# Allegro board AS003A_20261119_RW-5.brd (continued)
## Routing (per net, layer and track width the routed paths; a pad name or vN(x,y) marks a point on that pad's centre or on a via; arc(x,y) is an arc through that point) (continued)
D231_MCB1_CT2:
  vias: v1(180.11,297.94)
D431_MCB1_CT1:
  vias: v1(180.11,295.15)
D10101: length 119.1
  L05_DIG w0.081: 287.63,201.55 289.67,199.51 289.67,192.61 294.07,188.22 294.07,178.98 292.8,177.71 292.8,111.06 D101.01
  L05_DIG w0.102: 287.63,201.55 287.63,205.83 v1(287.23,206.23)
D10102: length 242.3
  L03_DIG w0.096: 298.03,201.55 298.03,201.53 298.05,201.51 298.05,201.08 298.64,200.49 299.02,200.49 300.17,199.34 300.17,189.72 301.57,188.32 301.57,178.57 305.12,175.02 305.12,166.06 304.4,165.34 304.4,112.25 294.99,102.84 294.99,87.93 296.56,86.36 302.52,86.36 304.06,87.9 304.06,105.98 307.95,109.86 307.95,144.51 308.72,145.29 310.6,145.29 312.5,143.39 312.5,117.55 311.54,116.59 311.54,100.72 D101.02
  L03_DIG w0.102: 298.03,201.55 298.03,202.63 v1(298.43,203.03)
D10103: length 119.2
  L05_DIG w0.081: 291.63,201.55 291.63,201.19 293.25,199.57 293.25,191.81 294.87,190.2 294.87,178.77 296.56,177.07 296.56,169.06 306.87,158.76 306.87,137.44 306.01,136.58 306.01,114.7 311.5,109.22 311.5,97.44 D101.03
  L05_DIG w0.102: 291.63,201.55 291.63,205.83 v1(291.23,206.23)
D10104: length 242.3
  L03_DIG w0.096: 298.43,201.55 298.43,201.53 298.41,201.51 298.41,201.24 298.8,200.85 299.18,200.85 300.54,199.49 300.54,189.87 301.94,188.47 301.94,178.72 305.49,175.17 305.49,165.91 304.77,165.19 304.77,112.1 295.36,102.69 295.36,88.08 296.71,86.73 302.37,86.73 303.69,88.06 303.69,106.13 307.58,110.01 307.58,144.67 308.57,145.66 310.76,145.66 312.87,143.55 312.87,117.4 311.91,116.44 311.91,101.47 312.95,100.43 313.59,100.43 D101.04
  L03_DIG w0.102: 298.43,201.55 v1(298.43,202.23)
D10105: length 119.9
  L05_DIG w0.081: D101.05 316.47,97.55 316.47,104.97 314.68,106.76 314.68,152.92 297.94,169.66 297.94,189.94 295.02,192.86 295.02,199.64 293.23,201.42 293.23,201.55
  L05_DIG w0.102: v1(292.83,206.23) 293.23,205.83 293.23,201.55
D10106: length 193.3
  L03_DIG w0.096: 300.83,201.55 300.83,201.53 300.85,201.51 300.85,200.56 302.17,199.24 302.17,189.88 304.45,187.6 304.45,182.94 305.95,181.45 319.62,181.45 329.72,171.35 329.72,111.68 328.77,110.73 327.31,110.73 326.12,111.92 326.12,136.43 322.21,140.34 319.92,140.34 317.87,138.29 317.87,130.26 323.21,124.92 323.21,101.7 321.86,100.36 321.34,100.36 D101.06
  L03_DIG w0.102: 300.83,201.55 v1(300.83,202.23)
D10107: length 190.1
  L07_DIG w0.081: D101.07 323.96,97.9 323.96,118.56 304.09,138.44 303.79,138.44 303.58,138.23 303.58,137.93 322.96,118.55 322.96,118.29 322.75,118.08 322.42,118.08 302.39,138.1 302.39,152.73 303.38,153.72 303.38,160.48 303.18,160.68 302.88,160.68 302.67,160.47 302.67,156.44 302.46,156.23 302.16,156.23 301.95,156.44 301.95,175.65 302.25,175.95 302.25,199.46 301.69,200.02 298.41,200.02 297.23,201.2 297.23,201.55
  L07_DIG w0.102: 297.23,201.55 297.23,205.03 v1(297.63,205.43)
D10108: length 193.3
  L03_DIG w0.096: 301.23,201.55 301.23,201.53 301.21,201.51 301.21,200.71 302.54,199.39 302.54,190.03 304.82,187.75 304.82,183.1 306.1,181.82 319.77,181.82 330.08,171.51 330.08,111.53 328.92,110.36 327.16,110.36 325.75,111.77 325.75,136.27 322.06,139.97 320.07,139.97 318.24,138.14 318.24,130.41 323.58,125.07 323.58,100.6 D101.08
  L03_DIG w0.102: 301.23,201.55 301.23,202.63 v1(300.83,203.03)
D10109: length 193.3
  L07_DIG w0.081: D101.09 326.45,97.73 326.45,121.18 306.76,140.88 306.46,140.88 306.25,140.67 306.25,140.37 324.7,121.92 324.7,121.63 324.49,121.42 324.19,121.42 304.65,140.96 304.65,153.12 308.27,156.74 308.27,163.13 308.07,163.33 307.77,163.33 307.55,163.11 307.55,157.46 307.34,157.25 307.05,157.25 306.84,157.46 306.84,188.06 304.65,190.25 304.65,199.28 302.93,201 299.16,201 298.83,201.33 298.83,201.55
  L07_DIG w0.102: v1(299.23,205.43) 298.83,205.03 298.83,201.55
D10110: length 122.7
  L03_DIG w0.096: D101.10 332.03,100.89 332.03,171.4 314.96,188.47 305.73,188.47 304.42,189.78 304.42,198.73 302.05,201.1 302.05,201.39 302.03,201.41 302.03,201.55
  L03_DIG w0.102: 302.03,201.55 302.03,202.63 v1(302.43,203.03)
D10111: length 242.3
  L07_DIG w0.081: 303.91,205.83 304.09,205.83 305.65,204.27 305.65,203.5 306.35,202.81 312.33,202.81 317.95,197.18 317.95,192.42 313.2,187.67 313.2,172.48 313.41,172.27 313.7,172.27 313.91,172.48 313.91,186.87 314.12,187.08 314.42,187.08 314.63,186.87 314.63,170.04 313.89,169.3 310.24,169.3 309.26,168.32 309.26,141.34 309.47,141.13 309.77,141.13 309.98,141.34 309.98,167.56 310.19,167.77 310.48,167.77 310.69,167.56 310.69,140.58 319.61,131.67 325.3,131.67 330.19,126.78 330.19,114.82 330.4,114.61 330.69,114.61 330.9,114.82 330.9,122.19 331.11,122.39 331.41,122.39 331.62,122.19 331.62,97.64 D101.11
  L07_DIG w0.102: 303.91,205.83 300.43,205.83 v1(300.03,206.23)
D10112: length 122.7
  L03_DIG w0.096: 302.43,201.55 302.43,201.24 304.79,198.88 304.79,189.93 305.88,188.84 315.11,188.84 332.4,171.56 332.4,101.04 333.18,100.26 334.08,100.26 D101.12
  L03_DIG w0.102: 302.43,201.55 v1(302.43,202.23)
D10113: length 131.6
  L07_DIG w0.081: D101.13 336.6,97.74 336.6,125.16 324.53,137.22 324.53,182.93 318.97,188.49 318.97,197.44 311.84,204.57 306.51,204.57 304.45,206.63 303.91,206.63
  L07_DIG w0.102: v1(300.03,207.03) 300.43,206.63 303.91,206.63
D10114: length 244.5
  L03_DIG w0.096: D101.14 341.85,100.55 343.71,100.55 343.98,100.82 343.98,111.82 348.17,116.01 348.17,155.62 347.07,156.72 340.15,156.72 338.82,155.39 338.82,110.28 337.7,109.16 335.95,109.16 334.99,110.13 334.99,171.49 333.16,173.32 333.16,199.44 330.8,201.8 314.79,201.8 312.14,204.45 305.27,204.45 304.47,205.25 304.15,205.25 303.93,205.03 303.91,205.03
  L03_DIG w0.102: 303.91,205.03 302.83,205.03 v1(302.43,205.43)
D10115: length 140.5
  L07_DIG w0.081: D101.15 341.7,97.72 341.7,123.99 327.32,138.37 327.32,189.27 326.56,190.03 326.56,200.86 325.37,202.06 316.09,202.06 311.65,206.5 305.97,206.5 305.03,207.43 303.91,207.43
  L07_DIG w0.102: v1(300.03,207.83) 300.43,207.43 303.91,207.43
D10116: length 244.5
  L03_DIG w0.096: D101.16 344.35,100.15 344.35,111.67 348.54,115.86 348.54,155.77 347.22,157.09 339.99,157.09 338.45,155.55 338.45,110.43 337.55,109.53 336.11,109.53 335.36,110.28 335.36,171.64 333.52,173.48 333.52,199.59 330.95,202.17 314.94,202.17 312.29,204.82 305.42,204.82 304.62,205.61 304.15,205.61 303.93,205.83 303.91,205.83
  L03_DIG w0.102: 303.91,205.83 302.13,205.83 302.03,205.73 302.03,205.03 v1(302.43,204.63)
D10201: length 212.5
  L30_DIG w0.081: 287.63,201.55 287.63,192.69 286.3,191.36 284,191.36 282.52,189.88 282.52,164.64 290.22,156.94 290.22,108.26 294.34,104.13 294.34,44.16 296.66,41.84 300.46,41.84 302.24,43.62 302.24,71.1 D102.01
  L30_DIG w0.102: 287.63,201.55 287.63,203.43 v1(288.03,203.83)
D10202: length 135.3
  L07_DIG w0.081: 294.03,201.55 294.03,200.38 294.76,199.66 294.76,191.36 294.06,190.66 294.06,178.04 295.42,176.67 295.42,157.18 293.86,155.61 293.86,129.16 305.91,117.11 305.91,82.71 D102.02
  L07_DIG w0.102: 294.03,201.55 294.03,205.03 v1(294.43,205.43)
D10203: length 138.4
  L07_DIG w0.081: D102.03 311.23,77.39 311.23,114.69 295,130.91 295,155.08 296.69,156.77 296.69,176.61 294.91,178.38 294.91,189.32 295.34,189.75 295.34,200.43 294.83,200.94 294.83,201.55
  L07_DIG w0.102: v1(295.23,205.43) 294.83,205.03 294.83,201.55
D10204: length 112.5
  L07_DIG w0.081: D102.04 313.68,80.02 313.68,117.99 297.9,133.77 297.9,181.94 K7.2
D10205: length 159.1
  L09_DIG w0.081: D102.05 316.28,77.42 316.28,108.99 319.25,111.96 319.25,153.73 319.98,154.46 319.98,168.01 325.35,173.38 325.35,189.52 326.7,190.87 326.7,201.14 323.84,204 317.42,204 316.43,204.99 315.29,204.99 311.81,208.47 306.14,208.47 305.58,209.03 303.91,209.03
  L09_DIG w0.102: 303.91,209.03 301.23,209.03 v1(300.83,209.43)
D10206: length 179.1
  L05_DIG w0.079: D102.06 321.39,80.09 322.21,80.09 322.76,80.64 322.76,81.6 321.09,83.27 321.09,105.11 323.06,107.08 323.06,123.19 322.11,124.14 320.91,124.14 319.88,123.12 319.88,107.15 319,106.27 317.75,106.27 316.96,107.07 316.96,134.69 319.06,136.79 319.06,152.94 304.66,167.34 304.66,175.97 301.4,179.22 301.4,188.88 296.65,193.64 296.65,201.19
  L05_DIG w0.102: 296.65,201.19 296.63,201.21 296.63,201.48 296.43,201.68 296.43,204.23 v1(296.83,204.63)
D10207: length 165
  L09_DIG w0.081: 303.91,209.83 312.02,209.83 315.89,205.95 325.56,205.95 331.3,200.21 331.3,194.11 329.83,192.64 329.83,175.39 322.47,168.03 322.47,136.81 324.51,134.76 324.51,124.4 321.35,121.23 321.35,77.43 D102.07
  L09_DIG w0.102: v1(300.83,210.23) 301.23,209.83 303.91,209.83
D10208: length 179.1
  L05_DIG w0.079: D102.08 323.14,80.72 323.14,81.76 321.47,83.43 321.47,104.95 323.45,106.92 323.45,123.35 322.27,124.52 320.75,124.52 319.5,123.28 319.5,107.31 318.84,106.65 317.91,106.65 317.34,107.23 317.34,134.53 319.45,136.63 319.45,153.1 305.04,167.5 305.04,176.13 301.79,179.38 301.79,189.04 297.03,193.8 297.03,201.19
  L05_DIG w0.102: v1(296.83,205.43) 297.23,205.03 297.23,201.68 297.03,201.48 297.03,201.19
D10209: length 165.9
  L09_DIG w0.081: D102.09 326.54,77.32 326.54,133.34 329.93,136.73 329.93,165.77 334.06,169.9 334.06,201.16 328.45,206.76 316.28,206.76 312.84,210.21 305.89,210.21 305.46,210.63 303.91,210.63
  L09_DIG w0.102: v1(300.83,211.03) 301.23,210.63 303.91,210.63
D10210: length 215.3
  L05_DIG w0.079: D102.10 332.17,80.71 332.17,82.46 331.31,83.31 331.31,106.07 332.43,107.18 332.43,139.74 331.83,140.34 329.52,140.34 328.8,139.63 328.8,106.81 327.78,105.79 325.96,105.79 324.87,106.88 324.87,149.89 307.79,166.97 307.79,186.79 304.33,190.25 304.33,195.79 302.28,197.84 301,197.84 300.15,198.69 300.15,199.37 299.81,199.72 299.38,199.72 298.25,200.84 298.25,201.23
  L05_DIG w0.102: 298.25,201.23 298.23,201.25 298.23,201.51 298.03,201.71 298.03,205.03 v1(298.43,205.43)
D10211: length 170.2
  L09_DIG w0.081: 303.91,211.43 313.13,211.43 316.97,207.59 329.96,207.59 339.71,197.84 339.71,140.29 331.56,132.14 331.56,77.38 D102.11
  L09_DIG w0.102: v1(300.83,211.83) 301.23,211.43 303.91,211.43
D10212: length 215.2
  L05_DIG w0.079: 298.63,201.23 298.63,201 299.54,200.1 299.97,200.1 300.53,199.53 300.53,198.85 301.16,198.22 302.44,198.22 304.72,195.94 304.72,190.41 308.18,186.95 308.18,167.12 325.25,150.05 325.25,107.04 326.12,106.18 327.62,106.18 328.42,106.97 328.42,139.78 329.36,140.73 331.99,140.73 332.81,139.9 332.81,107.02 331.7,105.91 331.7,83.47 332.55,82.62 332.55,80.65 333.24,79.96 334.06,79.96 D102.12
  L05_DIG w0.102: v1(298.43,204.63) 298.83,204.23 298.83,201.71 298.63,201.51 298.63,201.23
D10213: length 175.8
  L09_DIG w0.081: D102.13 336.62,77.4 336.62,134.8 344.46,142.64 344.46,168.47 343.2,169.74 343.2,196.94 330.6,209.53 317.14,209.53 314.64,212.03 306.09,212.03 305.09,213.03 303.91,213.03
  L09_DIG w0.102: v1(299.23,212.63) 299.63,213.03 303.91,213.03
D10214: length 190.1
  L05_DIG w0.079: 300.65,201.21 300.65,200.74 301.18,200.21 316.48,200.21 318.68,198.01 318.68,188.65 321.06,186.27 336.86,186.27 352.89,170.23 352.89,141.08 365.1,128.87 365.1,89.99 357.89,82.78 343.82,82.78 343.01,81.96 343.01,80.49 342.45,79.93 341.55,79.93 D102.14
  L05_DIG w0.102: v1(300.83,204.63) 300.43,204.23 300.43,201.69 300.63,201.49 300.63,201.23 300.65,201.21
D10215: length 177
  L09_DIG w0.081: D102.15 341.72,77.38 341.72,135.52 347.41,141.21 347.41,168.2 344.89,170.73 344.89,198.98 333.5,210.37 317.89,210.37 314.43,213.83 303.91,213.83
  L09_DIG w0.102: v1(300.83,214.23) 301.23,213.83 303.91,213.83
D10216: length 190.1
  L05_DIG w0.079: D102.16 343.39,80.79 343.39,81.8 343.98,82.39 358.04,82.39 365.49,89.83 365.49,129.03 353.28,141.24 353.28,170.39 337.01,186.65 321.22,186.65 319.07,188.81 319.07,198.17 316.64,200.6 301.33,200.6 301.03,200.9 301.03,201.21
  L05_DIG w0.102: v1(300.83,205.43) 301.23,205.03 301.23,201.69 301.03,201.49 301.03,201.21
D10301: length 215.3
  L32_DIG w0.081: 298.83,201.55 298.83,201.25 299.87,200.21 301.06,200.21 302.17,199.1 302.17,135.27 276.43,109.53 276.43,41.23 280.75,36.91 288.37,36.91 D103.01
  L32_DIG w0.102: 298.83,201.55 298.83,202.63 v1(299.23,203.03)
D10302: length 209.9
  L30_DIG w0.081: D103.02 308.64,59.66 308.64,104.21 305.84,107.02 295.5,107.02 292.76,109.76 292.76,118.05 294.05,119.34 294.05,150.88 293.84,151.1 293.54,151.1 293.34,150.9 293.34,128.76 293.14,128.56 292.84,128.56 292.62,128.78 292.62,158.1 284.92,165.8 284.92,175.76 285.7,176.54 285.7,188.97 288.26,191.54 288.26,199.63 288.43,199.79 288.43,201.55
  L30_DIG w0.102: 288.43,201.55 288.43,203.43 v1(288.83,203.83)
D10303: length 153
  L32_DIG w0.081: D103.03 311.32,56.98 311.32,127.58 304.54,134.37 304.54,199.4 303.51,200.43 301.66,200.43 301.23,200.85 301.23,201.55
  L32_DIG w0.102: v1(301.63,203.03) 301.23,202.63 301.23,201.55
D10304: length 209.9
  L30_DIG w0.081: D103.04 313.68,59.7 313.68,109.17 309.47,113.38 303.15,113.38 297.91,118.62 297.91,141.77 297.7,141.98 297.4,141.98 297.19,141.77 297.19,119.08 296.98,118.87 296.68,118.87 296.47,119.08 296.47,142.97 297.91,144.41 297.91,154.94 286.8,166.04 286.8,176.05 288.78,178.03 288.78,190.28 289.52,191.02 289.52,199.93 289.23,200.22 289.23,201.55
  L30_DIG w0.102: 289.23,201.55 289.23,203.43 v1(289.63,203.83)
D10305: length 193.3
  L32_DIG w0.081: D103.05 316.33,57.05 316.33,107.29 324.65,115.6 324.65,136.87 322.36,139.16 322.36,174.71 318.72,178.36 318.72,192.68 318.51,192.88 318.22,192.88 318,192.66 318,182.97 317.79,182.76 317.49,182.76 317.28,182.97 317.28,201.09 311.74,206.63 303.91,206.63
  L32_DIG w0.102: 303.91,206.63 299.63,206.63 v1(299.23,206.23)
D10306: length 158.7
  L30_DIG w0.081: 290.83,201.55 290.83,200.31 290.06,199.54 290.06,184.6 289.6,184.14 289.6,166.68 302.3,153.97 302.3,125.5 318.81,109 318.81,59.65 D103.06
  L30_DIG w0.102: v1(291.23,203.83) 290.83,203.43 290.83,201.55
D10307: length 176.5
  L32_DIG w0.081: D103.07 321.54,56.92 321.54,108.49 327.78,114.72 327.78,189.03 326.66,190.16 326.66,201.44 325.19,202.91 316.86,202.91 311.59,208.17 305.25,208.17 304.51,207.43 303.91,207.43
  L32_DIG w0.102: v1(302.43,207.83) 302.83,207.43 303.91,207.43
D10308: length 179.1
  L30_DIG w0.081: 291.63,201.55 291.63,200.03 291.26,199.67 291.26,184.33 290.42,183.48 290.42,178.13 292.55,176 292.55,165.8 304.52,153.83 304.52,131.07 312.52,123.07 312.82,123.07 313.03,123.28 313.03,123.58 307.26,129.34 307.26,129.63 307.47,129.84 307.77,129.84 323.87,113.75 323.87,59.67 D103.08
  L30_DIG w0.102: v1(292.03,203.83) 291.63,203.43 291.63,201.55
D10309: length 180.5
  L32_DIG w0.081: D103.09 326.52,57.02 326.52,107.17 330.47,111.13 330.47,189.56 331.7,190.79 331.7,199.99 327.41,204.28 317.49,204.28 312.03,209.74 306.03,209.74 305.32,209.03 303.91,209.03
  L32_DIG w0.102: 303.91,209.03 302.83,209.03 v1(302.43,209.43)
D10310: length 179.1
  L30_DIG w0.081: D103.10 328.8,59.82 328.8,114.14 310.55,132.39 310.26,132.39 310.05,132.18 310.05,131.88 315.36,126.57 315.36,126.25 315.15,126.04 314.87,126.04 306.86,134.05 306.86,155.64 296.65,165.85 296.65,175.31 294.09,177.86 294.09,189.29 291.84,191.54 291.84,199.39 292.43,199.98 292.43,201.55
  L30_DIG w0.102: v1(292.83,203.83) 292.43,203.43 292.43,201.55
D10311: length 183.4
  L32_DIG w0.081: D103.11 331.68,56.94 331.68,104.77 333.21,106.3 333.21,154.7 331.61,156.31 331.61,167.83 332.87,169.09 332.87,202.15 329.1,205.92 316.85,205.92 312.59,210.18 311.24,210.18 309.88,211.54 306.06,211.54 305.15,210.63 303.91,210.63
  L32_DIG w0.102: 303.91,210.63 302.83,210.63 v1(302.43,211.03)
D10312: length 188.5
  L30_DIG w0.081: 293.23,201.55 293.23,191.63 294.92,189.94 294.92,178.57 297.86,175.64 297.86,169.5 309.1,158.25 309.1,137.05 320.27,125.89 320.54,125.89 320.75,126.1 320.75,126.42 312.57,134.59 312.57,134.89 312.78,135.1 313.08,135.1 334,114.18 334,59.7 D103.12
  L30_DIG w0.102: 293.23,201.55 293.23,203.43 v1(293.63,203.83)
D10313: length 184.5
  L32_DIG w0.081: 303.91,212.23 306.05,212.23 306.26,212.02 311.96,212.02 317.22,206.75 330.62,206.75 334.5,202.87 334.5,168.58 335.25,167.83 335.25,105.11 336.64,103.73 336.64,57.06 D103.13
  L32_DIG w0.102: v1(302.43,212.63) 302.83,212.23 303.91,212.23
D10314: length 188.5
  L30_DIG w0.081: D103.14 339.14,59.64 339.14,115.94 327.68,127.4 327.68,127.69 327.89,127.9 328.18,127.9 335.77,120.32 336.06,120.32 336.27,120.53 336.27,120.83 310.27,146.83 310.27,168.62 302.95,175.94 300.43,175.94 297.84,178.53 297.84,189.12 295.2,191.76 295.2,199.91 294.83,200.29 294.83,201.55
  L30_DIG w0.102: 294.83,201.55 294.83,203.43 v1(295.23,203.83)
D10315: length 188.1
  L32_DIG w0.081: D103.15 341.71,57.07 341.71,124.16 337.47,128.4 337.47,201.3 331.06,207.71 317.21,207.71 311.09,213.83 303.91,213.83
  L32_DIG w0.102: v1(302.43,214.23) 302.83,213.83 303.91,213.83
D10316: length 209.5
  L30_DIG w0.081: 295.63,201.55 295.63,200.55 296.8,199.38 296.8,193.02 301.11,188.7 301.11,179.62 311.73,169 311.73,147 341.97,116.76 342.27,116.76 342.48,116.97 342.48,117.27 328,131.75 328,132.04 328.21,132.25 328.51,132.25 344.19,116.57 344.19,59.67 D103.16
  L30_DIG w0.102: v1(296.03,203.83) 295.63,203.43 295.63,201.55
D10401: length 184.6
  L34_DIG w0.102: v1(288.83,206.23) 288.43,205.83 288.43,201.55
  L34_DIG w0.104: 288.43,201.55 288.43,199.75 288.21,199.54 288.21,192.07 285.74,189.6 283.85,189.6 282.62,188.37 282.62,173.53 293.46,162.69 293.46,49.44 D104.01
D10402: length 209.9
  L34_DIG w0.102: v1(289.63,202.23) 289.63,201.55
  L34_DIG w0.104: D104.02 303.18,44.8 303.18,63.14 303.39,63.35 303.7,63.35 303.92,63.14 303.92,47.27 304.18,47.01 304.49,47.01 304.66,47.17 304.66,153.06 287.2,170.51 287.2,174.6 285.84,175.96 285.84,188.64 289.63,192.43 289.63,201.55
D10403: length 177.5
  L34_DIG w0.102: 290.43,201.55 v1(290.43,202.23)
  L34_DIG w0.104: 290.43,201.55 290.43,200.48 291.14,199.77 291.14,191.42 289.09,189.37 289.09,172.58 310.23,151.45 310.23,108.4 311.32,107.31 311.32,36.66 D104.03
D10404: length 175.5
  L34_DIG w0.102: 291.23,201.55 v1(291.23,202.23)
  L34_DIG w0.104: D104.04 313.64,39.42 313.64,109.01 311.8,110.85 311.8,151.79 289.95,173.64 289.95,184.68 291.83,186.55 291.83,199.93 291.23,200.53 291.23,201.55
D10405: length 179.1
  L34_DIG w0.102: 292.03,201.55 v1(292.03,202.23)
  L34_DIG w0.104: D104.05 316.25,36.81 316.25,110.17 312.79,113.63 312.79,152.72 292.46,173.05 292.46,176.04 290.67,177.83 290.67,184.2 292.99,186.52 292.99,199.52 292.03,200.48 292.03,201.55
D10406: length 192
  L34_DIG w0.102: v1(293.63,206.23) 293.23,205.83 293.23,201.55
  L34_DIG w0.104: D104.06 318.63,39.51 318.63,111.61 314.67,115.56 314.67,139.15 316.79,141.26 316.79,153.6 317.77,154.59 317.77,168.46 314.84,171.4 297.66,171.4 296.74,172.32 296.74,174.53 294.08,177.19 294.08,183.39 293.61,183.87 293.61,199.99 293.23,200.37 293.23,201.55
D10407: length 195.5
  L34_DIG w0.102: 294.03,201.55 294.03,205.83 v1(294.43,206.23)
  L34_DIG w0.104: 294.03,201.55 294.03,200.47 294.8,199.7 294.8,178.08 297.13,175.74 315.4,175.74 319.97,171.17 319.97,154.88 319.15,154.06 319.15,137.73 317.38,135.96 317.38,127.78 319.94,125.23 319.94,113.81 321.44,112.31 321.44,36.7 D104.07
D10408: length 188.5
  L34_DIG w0.102: v1(295.23,202.23) 295.23,201.55
  L34_DIG w0.104: D104.08 323.72,39.5 323.72,112.34 321.88,114.18 321.88,126.33 318.68,129.54 318.68,133.56 322.49,137.38 322.49,170.13 315.54,177.09 300.4,177.09 298.09,179.4 298.09,190.52 295.23,193.37 295.23,201.55
D10409: length 209.5
  L34_DIG w0.102: v1(296.03,202.23) 296.03,201.55
  L34_DIG w0.104: D104.09 326.39,36.83 326.39,127.95 326.07,128.27 325.24,128.27 325.04,128.08 325.04,118 324.83,117.79 324.4,117.79 324.18,118.01 324.18,173.59 317.33,180.44 303.59,180.44 301.41,182.62 301.41,188.62 297.07,192.96 297.07,199.97 296.03,201.01 296.03,201.55
D10410: length 190.1
  L34_DIG w0.102: v1(296.83,206.23) 297.23,205.83 297.23,201.55
  L34_DIG w0.104: 297.23,201.55 297.23,201.17 298.65,199.76 298.65,195.62 302.31,191.95 302.31,187.1 304.83,184.57 304.83,182.97 305.51,182.29 319.39,182.29 327.7,173.97 327.7,103.55 328.86,102.39 328.86,39.44 D104.10
D10411: length 193.3
  L34_DIG w0.102: 298.03,201.55 298.03,205.83 v1(297.63,206.23)
  L34_DIG w0.104: D104.11 331.57,36.73 331.57,103.1 329.37,105.29 329.37,174.34 318.33,185.38 306.6,185.38 304.15,187.83 304.15,192.16 302.39,193.92 302.39,198.93 301.64,199.68 299.62,199.68 298.03,201.27 298.03,201.55
D10412: length 215.2
  L34_DIG w0.102: v1(299.23,202.23) 299.23,201.55
  L34_DIG w0.104: D104.12 333.86,39.52 333.86,107.21 330.88,110.19 330.88,124.52 331.1,124.74 331.4,124.74 331.62,124.52 331.62,112.48 331.85,112.25 332.16,112.25 332.36,112.45 332.36,177.05 323.04,186.38 309.5,186.38 308.06,187.82 308.06,188.86 305.12,191.8 305.12,196.23 303.97,197.38 303.97,199.51 303.02,200.46 300.15,200.46 299.23,201.38 299.23,201.55
D10413: length 191.7
  L34_DIG w0.102: 300.03,201.55 v1(300.03,202.23)
  L34_DIG w0.104: 300.03,201.55 300.31,201.27 303.42,201.27 304.83,199.86 304.83,197.67 306.91,195.59 306.91,191.98 311,187.89 323.95,187.89 334.93,176.92 334.93,110.89 336.64,109.19 336.64,36.74 D104.13
D10414: length 188.9
  L34_DIG w0.102: 303.91,202.19 303.87,202.23 v1(303.23,202.23)
  L34_DIG w0.104: D104.14 339.11,39.35 339.11,136.81 339.79,137.49 339.79,179.04 330.58,188.24 326.02,188.24 324.35,189.91 320.36,189.91 318.82,191.44 318.82,193.08 311.77,200.14 305.97,200.14 303.91,202.19
D10415: length 199.1
  L34_DIG w0.102: 303.91,203.03 v1(303.23,203.03)
  L34_DIG w0.104: D104.15 341.82,36.64 341.82,134.84 347.97,140.99 347.97,175.46 332.58,190.85 327.48,190.85 326.16,192.18 320.39,192.18 309.99,202.58 305.22,202.58 304.77,203.03 303.91,203.03
D10416: length 199.9
  L34_DIG w0.102: 303.91,203.83 v1(303.23,203.83)
  L34_DIG w0.104: 303.91,203.83 305.13,203.83 305.89,203.07 311,203.07 321.09,192.98 332.81,192.98 334.89,190.9 337.08,190.9 349.62,178.35 349.62,129.63 344.26,124.27 344.26,39.28 D104.16
D10501: length 181.6
  L05_DIG w0.081: D105.01 373.28,104.24 373.28,194.88 364.78,203.38 318.13,203.38 313.37,208.15 305.81,208.15 304.93,209.03 303.91,209.03
  L05_DIG w0.102: 303.91,209.03 299.63,209.03 v1(299.23,209.43)
D10502: length 314.6
  L03_DIG w0.096: 303.91,207.03 303.93,207.03 303.95,207.05 304.61,207.05 305.41,206.24 312.68,206.24 315.58,203.34 333.23,203.34 335.24,201.33 387.98,201.33 393.86,195.45 393.86,136.05 392.9,135.09 391.71,135.09 390.58,136.22 390.58,191.16 389.1,192.63 387.12,192.63 385.88,191.4 385.88,137.01 386.74,136.16 386.74,100.77 386.46,100.49 384.97,100.49 D105.02
  L03_DIG w0.102: 303.91,207.03 v1(303.23,207.03)
D10503: length 190
  L07_DIG w0.081: D105.03 384.97,97.63 384.97,194.54 380.56,198.95 374.57,198.95 373.25,200.26 335.3,200.26 331.62,203.94 317.46,203.94 311.85,209.55 305.39,209.55 304.86,209.03 303.91,209.03
  L07_DIG w0.102: 303.91,209.03 300.43,209.03 v1(300.03,209.43)
D10504: length 314.6
  L03_DIG w0.096: D105.04 387.11,100.57 387.11,136.31 386.25,137.16 386.25,191.24 387.28,192.27 388.95,192.27 390.21,191.01 390.21,136.07 391.56,134.72 393.05,134.72 394.23,135.9 394.23,195.6 388.13,201.7 335.4,201.7 333.39,203.71 315.73,203.71 312.84,206.61 305.57,206.61 304.76,207.41 303.95,207.41 303.93,207.43 303.91,207.43
  L03_DIG w0.102: v1(302.43,207.03) 302.83,207.43 303.91,207.43
D10505: length 194.5
  L07_DIG w0.081: 303.91,210.63 304.07,210.63 304.56,210.14 312.61,210.14 316.36,206.39 331.1,206.39 336.13,201.36 381.86,201.36 390.16,193.06 390.16,97.52 D105.05
  L07_DIG w0.102: 303.91,210.63 300.43,210.63 v1(300.03,211.03)
D10506: length 314.6
  L03_DIG w0.096: 303.91,208.23 303.93,208.23 303.95,208.25 305,208.25 305.24,208 315.97,208 317.06,206.91 332.37,206.91 336.29,202.99 423.51,202.99 424.26,202.24 424.26,201.11 423.66,200.51 394.78,200.51 393.73,199.46 393.73,198.08 394.78,197.03 424.17,197.03 425.03,196.17 425.03,194.46 423.83,193.27 399.53,193.27 395.83,189.56 395.83,101.19 D105.06
  L03_DIG w0.102: 303.91,208.23 302.83,208.23 v1(302.43,208.63)
D10507: length 199.7
  L07_DIG w0.081: 303.91,211.43 313.15,211.43 317,207.59 331.7,207.59 336.61,202.68 385.29,202.68 395.29,192.68 395.29,97.47 D105.07
  L07_DIG w0.102: 303.91,211.43 300.43,211.43 v1(300.03,211.83)
D10508: length 314.6
  L03_DIG w0.096: 303.91,208.63 303.93,208.63 303.95,208.61 305.15,208.61 305.4,208.37 316.13,208.37 317.22,207.27 332.52,207.27 336.44,203.36 423.66,203.36 424.63,202.39 424.63,200.96 423.81,200.14 394.93,200.14 394.1,199.3 394.1,198.23 394.93,197.4 424.32,197.4 425.4,196.32 425.4,194.31 423.98,192.9 399.69,192.9 396.2,189.41 396.2,101.34 397.25,100.29 397.55,100.29 D105.08
  L03_DIG w0.102: 303.91,208.63 v1(303.23,208.63)
D10509: length 207.5
  L07_DIG w0.081: D105.09 400.24,97.6 400.24,137.59 401.66,139.01 401.66,193.38 391.23,203.81 375.7,203.81 372.87,206.64 334.6,206.64 331.64,209.6 317.26,209.6 315.03,211.83 305.7,211.83 305.3,212.23 303.91,212.23
  L07_DIG w0.102: 303.91,212.23 300.43,212.23 v1(300.03,212.63)
D10510: length 314.6
  L03_DIG w0.096: 303.91,210.23 303.93,210.23 303.95,210.25 304.69,210.25 305.18,209.76 313.57,209.76 314.02,210.2 331.76,210.2 335.6,206.36 338.9,206.36 339.47,205.8 423.08,205.8 427.97,200.91 427.97,159.67 427.14,158.84 425.77,158.84 424.74,159.87 424.74,189.44 422.65,191.53 411.09,191.53 408.82,189.25 408.82,130.83 407.08,129.09 407.08,100.79 406.82,100.54 405.34,100.54 D105.10
  L03_DIG w0.102: 303.91,210.23 v1(303.23,210.23)
D10511: length 211.4
  L07_DIG w0.081: D105.11 405.19,97.73 405.19,192.51 391.64,206.06 375.5,206.06 373.81,207.75 335.07,207.75 332.28,210.54 318.05,210.54 315.14,213.45 304.91,213.45 304.53,213.83 303.91,213.83
  L07_DIG w0.102: v1(299.23,213.43) 299.63,213.83 303.91,213.83
D10512: length 314.6
  L03_DIG w0.096: D105.12 407.44,100.56 407.44,128.94 409.18,130.68 409.18,189.1 411.25,191.16 422.5,191.16 424.37,189.29 424.37,159.72 425.62,158.47 427.3,158.47 428.34,159.52 428.34,201.06 423.24,206.17 339.62,206.17 339.06,206.73 335.75,206.73 331.91,210.57 313.86,210.57 313.42,210.12 305.33,210.12 304.84,210.61 303.95,210.61 303.93,210.63 303.91,210.63
  L03_DIG w0.102: 303.91,210.63 302.83,210.63 v1(302.43,210.23)
D10513: length 215.7
  L07_DIG w0.081: D105.13 410.31,97.69 410.31,189.48 391.68,208.11 375.83,208.11 375.08,208.86 336.19,208.86 333.6,211.45 319.42,211.45 315.52,215.35 305.1,215.35 304.39,214.63 303.91,214.63
  L07_DIG w0.102: v1(299.23,214.23) 299.63,214.63 303.91,214.63
D10514: length 314.6
  L03_DIG w0.096: D105.14 416.12,101.16 416.12,153.44 418.26,155.58 423.5,155.58 426.11,152.96 426.11,122.24 426.99,121.36 428.96,121.36 430.29,122.69 430.29,201.76 423.97,208.08 336.05,208.08 332.06,212.06 313.33,212.06 312.71,211.45 303.95,211.45 303.93,211.43 303.91,211.43
  L03_DIG w0.102: v1(302.43,211.83) 302.83,211.43 303.91,211.43
D10515: length 220.2
  L07_DIG w0.081: 303.91,215.43 305.52,217.03 315.33,217.03 319.84,212.53 373.25,212.53 375.13,210.65 392.75,210.65 415.47,187.93 415.47,97.61 D105.15
  L07_DIG w0.102: 303.91,215.43 300.43,215.43 v1(300.03,215.83)
D10516: length 314.6
  L03_DIG w0.096: 303.91,211.83 303.93,211.83 303.95,211.81 312.56,211.81 313.18,212.43 332.22,212.43 336.2,208.45 424.12,208.45 430.65,201.92 430.65,122.54 429.11,120.99 426.84,120.99 425.75,122.09 425.75,152.81 423.34,155.21 418.42,155.21 416.49,153.28 416.49,101.43 417.64,100.28 417.88,100.28 D105.16
  L03_DIG w0.102: 303.91,211.83 v1(303.23,211.83)
D10601: length 192.4
  L07_DIG w0.081: 303.91,208.23 311.42,208.23 316.68,202.98 330.04,202.98 335.69,197.32 356.5,197.32 374.19,179.64 374.19,83.01 D106.01
  L07_DIG w0.102: 303.91,208.23 300.43,208.23 v1(300.03,208.63)
D10602: length 204
  L09_DIG w0.081: D106.02 382.21,80.07 382.21,104.93 374.1,113.04 374.1,195.59 360.84,208.85 336.88,208.85 334.15,211.58 319.17,211.58 315.32,215.43 303.91,215.43
  L09_DIG w0.102: 303.91,215.43 299.63,215.43 v1(299.23,215.03)
D10603: length 219.1
  L09_DIG w0.081: 303.91,217.03 315.63,217.03 320.11,212.55 370.17,212.55 374.46,208.26 380.84,208.26 381.96,207.13 381.96,160.64 383.36,159.24 383.36,137.53 382.06,136.23 382.06,109.06 384.97,106.15 384.97,77.31 D106.03
  L09_DIG w0.102: 303.91,217.03 301.23,217.03 v1(300.83,217.43)
D10604: length 220.6
  L09_DIG w0.081: 303.91,218.63 316.96,218.63 319.6,215.99 338.19,215.99 340.46,213.73 372.33,213.73 375.5,210.56 381.67,210.56 384.86,207.37 384.86,109.55 387.34,107.07 387.34,80.02 D106.04
  L09_DIG w0.102: v1(299.23,219.03) 299.63,218.63 303.91,218.63
D10605: length 257.7
  L09_DIG w0.081: 303.91,220.23 305.13,220.23 305.65,220.75 323.99,220.75 325.81,218.92 339.12,218.92 340.54,217.51 344.83,217.51 345.8,218.48 349.43,218.48 352.75,215.16 375.21,215.16 377.45,212.92 385.38,212.92 390.01,208.29 390.01,125.88 390.23,125.66 390.53,125.66 390.73,125.87 390.73,139.47 390.94,139.68 391.24,139.68 391.45,139.47 391.45,108.81 390.01,107.38 390.01,77.35 D106.05
  L09_DIG w0.102: 303.91,220.23 301.23,220.23 v1(300.83,219.83)
D10606: length 314.6
  L05_DIG w0.079: D106.06 395.01,80.05 396.53,80.05 396.7,80.21 396.7,81.34 394.77,83.26 394.77,113.02 413.92,132.16 413.92,180.69 415.52,182.3 419.26,182.3 420.76,180.8 420.76,164.03 421.79,163 425.87,163 426.7,163.83 426.7,202.23 423.12,205.82 366.97,205.82 366.42,206.36 316.98,206.36 314.74,208.6 314.74,210.52 312.03,213.24 304.14,213.24 303.93,213.03 303.91,213.03
  L05_DIG w0.102: 303.91,213.03 301.23,213.03 v1(300.83,213.43)
D10607: length 328.2
  L09_DIG w0.081: D106.07 395.06,77.38 395.06,104.42 393.63,105.86 393.63,154.32 393.84,154.53 394.14,154.53 394.35,154.32 394.35,109.08 394.56,108.86 394.86,108.86 395.06,109.06 395.06,208.41 387.87,215.6 378.19,215.6 371.81,221.98 352.86,221.98 350.63,219.75 342.35,219.75 341.66,220.43 335.1,220.43 334.49,219.81 326.29,219.81 323.47,222.63 303.91,222.63
  L09_DIG w0.102: 303.91,222.63 301.23,222.63 v1(300.83,223.03)
D10608: length 314.6
  L05_DIG w0.079: 303.91,213.83 303.93,213.83 304.14,213.62 312.19,213.62 315.13,210.68 315.13,208.76 317.14,206.74 366.58,206.74 367.13,206.2 423.28,206.2 427.09,202.39 427.09,163.67 426.03,162.61 421.63,162.61 420.37,163.88 420.37,180.64 419.1,181.91 415.68,181.91 414.31,180.53 414.31,132.01 395.16,112.86 395.16,83.42 397.08,81.5 397.08,80.44 D106.08
  L05_DIG w0.102: 303.91,213.83 300.43,213.83 v1(300.03,213.43)
D10609: length 266.2
  L09_DIG w0.081: 303.91,223.43 305.18,223.43 305.9,224.16 324.26,224.16 325.33,223.09 336.84,223.09 338.27,224.52 352.53,224.52 352.74,224.31 352.74,224.01 352.53,223.8 339.2,223.8 339,223.6 339,223.3 339.22,223.09 372.61,223.09 378.65,217.05 388.46,217.05 400.09,205.43 400.09,77.43 D106.09
  L09_DIG w0.102: 303.91,223.43 301.23,223.43 v1(300.83,223.83)
D10610: length 314.6
  L05_DIG w0.079: D106.10 405.16,80.04 406.56,80.04 406.95,80.43 406.95,81.4 404.86,83.48 404.86,106.59 419.03,120.76 419.03,159.84 420.39,161.2 423.62,161.2 424.98,159.84 424.98,142.85 426.19,141.64 428.19,141.64 429.8,143.26 429.8,203.96 425.65,208.11 334.99,208.11 333.42,209.68 318.25,209.68 312.83,215.1 306.07,215.1 305.81,214.84 304.14,214.84 303.93,214.63 303.91,214.63
  L05_DIG w0.102: v1(300.83,215.03) 301.23,214.63 303.91,214.63
D10611: length 266.2
  L09_DIG w0.081: D106.11 405.16,77.44 405.16,202.89 393.51,214.54 393.51,231.62 389.5,235.63 378.22,235.63 376.7,237.14 363.49,237.14 362.85,236.5 351.36,236.5 350.02,237.84 339.68,237.84 339.14,238.38 336.99,238.38 335.84,237.23 321.88,237.23 314.77,230.12 301.06,230.12 299.63,228.7 299.63,227.71
  L09_DIG w0.102: 299.63,227.71 299.63,225.03 v1(299.23,224.63)
D10612: length 314.6
  L05_DIG w0.079: D106.12 407.33,80.35 407.33,81.56 405.25,83.64 405.25,106.43 419.42,120.6 419.42,159.68 420.55,160.82 423.46,160.82 424.6,159.68 424.6,142.69 426.03,141.26 428.35,141.26 430.19,143.1 430.19,204.12 425.81,208.49 335.15,208.49 333.58,210.06 318.41,210.06 312.99,215.48 305.91,215.48 305.65,215.22 304.14,215.22 303.93,215.43 303.91,215.43
  L05_DIG w0.102: 303.91,215.43 300.43,215.43 v1(300.03,215.03)
D10613: length 274.9
  L09_DIG w0.081: D106.13 410.29,77.39 410.29,200.51 394.71,216.09 394.71,234.84 390.38,239.17 382.03,239.17 381.02,240.18 378.02,240.18 377.58,240.62 361.16,240.62 359.87,241.91 354.45,241.91 354.06,242.31 351.48,242.31 349.76,240.58 309.88,240.58 298.83,229.53 298.83,227.71
  L09_DIG w0.102: v1(298.43,224.63) 298.83,225.03 298.83,227.71
D10614: length 314.6
  L05_DIG w0.079: D106.14 415.32,80.04 416.63,80.04 417.18,80.58 417.18,82.12 417.85,82.79 422.67,82.79 424.66,84.78 424.66,137.59 425.82,138.74 427.41,138.74 428.55,137.61 428.55,121.02 429.96,119.61 431.52,119.61 432.45,120.54 432.45,205.06 427.15,210.37 368.81,210.37 366.82,212.36 318.5,212.36 313.98,216.89 306.03,216.89 305.58,216.44 304.14,216.44 303.93,216.23 303.91,216.23
  L05_DIG w0.102: 303.91,216.23 301.23,216.23 v1(300.83,216.63)
D10615: length 297.3
  L09_DIG w0.081: D106.15 415.37,77.39 415.37,197.96 396.16,217.17 396.16,248.75 391.07,253.84 377.81,253.84 377.19,254.46 322.31,254.46 298.03,230.17 298.03,227.71
  L09_DIG w0.102: v1(297.63,224.63) 298.03,225.03 298.03,227.71
D10616: length 314.6
  L05_DIG w0.079: 303.91,217.03 303.93,217.03 304.14,216.82 305.42,216.82 305.87,217.27 314.13,217.27 318.66,212.75 366.98,212.75 368.97,210.75 427.3,210.75 432.84,205.22 432.84,120.38 431.68,119.22 429.8,119.22 428.17,120.86 428.17,137.45 427.25,138.36 425.98,138.36 425.04,137.43 425.04,84.62 422.83,82.41 418.01,82.41 417.56,81.96 417.56,80.28 D106.16
  L05_DIG w0.102: v1(300.03,216.63) 300.43,217.03 303.91,217.03
D10701: length 213.5
  L32_DIG w0.081: D107.01 377.44,59.44 377.44,120.41 352.62,145.23 352.62,201.43 345.77,208.29 340.59,208.29 339.6,209.27 318.11,209.27 312.35,215.03 305.77,215.03 305.37,214.63 303.91,214.63
  L32_DIG w0.102: v1(302.43,215.03) 302.83,214.63 303.91,214.63
D10702: length 209.5
  L30_DIG w0.081: 296.43,201.55 296.43,201.35 298.57,199.21 298.57,192.92 302.04,189.45 302.04,187.06 308.82,180.28 356.43,180.28 368.2,168.51 368.2,126.65 382.31,112.53 382.31,59.65 D107.02
  L30_DIG w0.102: 296.43,201.55 296.43,203.43 v1(296.83,203.83)
D10703: length 221.6
  L32_DIG w0.081: 303.91,216.23 305.11,216.23 305.83,215.51 313.35,215.51 318.81,210.05 348.2,210.05 355.08,203.16 355.08,171.43 358.39,168.12 358.39,154.49 384.81,128.07 384.81,57.15 D107.03
  L32_DIG w0.102: v1(299.23,215.83) 299.63,216.23 303.91,216.23
D10704: length 215.2
  L30_DIG w0.081: D107.04 387.41,59.63 387.41,112.46 370.78,129.08 370.78,171.18 360.44,181.53 311.89,181.53 311.68,181.74 311.68,182.04 312,182.36 312,182.74 311.78,182.96 308.58,182.96 304.57,186.97 304.57,189.91 303.64,190.84 302.23,190.84 300.4,192.68 300.4,199.08 298.26,201.21 297.57,201.21 297.23,201.55
  L30_DIG w0.102: v1(297.63,203.83) 297.23,203.43 297.23,201.55
D10705: length 225.1
  L32_DIG w0.081: 303.91,217.03 314.2,217.03 319.84,211.38 354.24,211.38 360.07,205.55 360.07,156.33 389.89,126.51 389.89,57.15 D107.05
  L32_DIG w0.102: 303.91,217.03 302.83,217.03 v1(302.43,217.43)
D10706: length 215.3
  L30_DIG w0.081: D107.06 392.46,59.66 392.46,113.51 372.72,133.26 372.72,170.94 357.73,185.93 309.33,185.93 308.02,187.24 308.02,189.18 306.45,190.75 305.24,190.75 304.47,191.52 304.47,194.18 303.98,194.67 302.89,194.67 302.36,195.2 302.36,199.2 301.81,199.74 300.63,199.74 298.83,201.55
  L30_DIG w0.102: v1(299.23,203.83) 298.83,203.43 298.83,201.55
D10707: length 230.6
  L32_DIG w0.081: 303.91,218.63 313.92,218.63 320.1,212.46 357.76,212.46 363.13,207.09 363.13,155.72 394.94,123.92 394.94,57.18 D107.07
  L32_DIG w0.102: v1(302.43,219.03) 302.83,218.63 303.91,218.63
D10708: length 229.4
  L30_DIG w0.081: D107.08 397.55,59.65 397.55,113.72 395.53,115.73 395.53,172.44 380.93,187.04 374.46,187.04 373.98,187.52 319.71,187.52 318.35,188.87 309.85,188.87 306.78,191.94 306.78,194.01 306.04,194.75 305.27,194.75 304.86,195.16 304.86,199.35 303.82,200.38 300.79,200.38 299.63,201.55
  L30_DIG w0.102: v1(300.03,203.83) 299.63,203.43 299.63,201.55
D10709: length 257.7
  L32_DIG w0.081: D107.09 400.09,57.11 400.09,104.6 398.66,106.03 398.66,120.89 398.87,121.1 399.16,121.1 399.37,120.89 399.37,112.66 399.59,112.45 399.94,112.45 400.09,112.6 400.09,124.5 365.47,159.12 365.47,208.59 360.26,213.8 340.08,213.8 338,215.88 319.88,215.88 315.54,220.23 303.91,220.23
  L32_DIG w0.102: v1(299.23,219.83) 299.63,220.23 303.91,220.23
D10710: length 236.3
  L30_DIG w0.081: 300.43,201.55 300.67,201.31 311.22,201.31 318.93,193.6 375.08,193.6 375.96,194.48 385.22,194.48 386.43,193.27 389.2,193.27 399.96,182.51 399.96,117.49 402.58,114.87 402.58,59.7 D107.10
  L30_DIG w0.102: 300.43,201.55 300.43,203.43 v1(300.83,203.83)
D10711: length 282.4
  L32_DIG w0.081: D107.11 405.27,57.01 405.27,102.05 403.84,103.48 403.84,123.34 404.05,123.55 404.35,123.55 404.56,123.34 404.56,104.82 404.76,104.61 405.06,104.61 405.27,104.83 405.27,124.74 398.48,131.53 398.48,133.92 369.45,162.96 369.45,210.76 362.15,218.06 358.73,218.06 358.02,217.35 354.2,217.35 353.32,218.23 345.22,218.23 344.27,217.28 337.17,217.28 335.52,218.93 321.1,218.93 319.18,220.85 306.01,220.85 305.83,221.03 303.91,221.03
  L32_DIG w0.102: v1(302.43,221.43) 302.83,221.03 303.91,221.03
D10712: length 236.7
  L30_DIG w0.081: 303.91,203.43 305.71,203.43 306.14,203 311.28,203 318.72,195.55 372.93,195.55 373.95,196.57 387.49,196.57 403.56,180.5 403.56,139.88 407.56,135.88 407.56,59.8 D107.12
  L30_DIG w0.102: 303.91,203.43 302.03,203.43 v1(301.63,203.83)
D10713: length 247.7
  L32_DIG w0.081: 303.91,222.63 319,222.63 321.53,220.1 328.64,220.1 328.85,219.89 331.64,219.89 331.86,220.1 342.09,220.1 342.58,219.61 350.47,219.61 350.93,220.07 362.89,220.07 372.68,210.28 372.68,161.98 400.1,134.55 400.1,132.99 401.16,131.94 403.05,131.94 410.34,124.64 410.34,57.02 D107.13
  L32_DIG w0.102: v1(302.43,223.03) 302.83,222.63 303.91,222.63
D10714: length 242.3
  L30_DIG w0.081: D107.14 412.77,59.67 412.77,114.15 409.9,117.01 409.9,177.88 389.12,198.66 373.22,198.66 371.38,200.5 334.78,200.5 333.07,198.78 317.92,198.78 312.06,204.65 305.79,204.65 305.41,205.03 303.91,205.03
  L30_DIG w0.102: v1(301.63,205.43) 302.03,205.03 303.91,205.03
D10715: length 250.4
  L32_DIG w0.081: D107.15 415.42,57.02 415.42,122.52 373.77,164.17 373.77,211.47 362.1,223.15 321.47,223.15 320.37,224.24 305.99,224.24 305.2,225.03 303.91,225.03
  L32_DIG w0.102: v1(302.43,225.43) 302.83,225.03 303.91,225.03
D10716: length 244.5
  L30_DIG w0.081: D107.16 417.83,59.69 417.83,115.91 415.28,118.45 415.28,174.13 387.71,201.7 316.49,201.7 312.04,206.14 305.73,206.14 305.42,205.83 303.91,205.83
  L30_DIG w0.102: v1(301.63,206.23) 302.03,205.83 303.91,205.83
D10801: length 244.5
  L34_DIG w0.102: 303.91,204.63 v1(303.23,204.63)
  L34_DIG w0.104: D108.01 370.11,24.67 357.26,24.67 350.73,31.2 350.73,180.9 338.79,192.85 334.56,192.85 331.79,195.63 320.54,195.63 311.8,204.37 305.73,204.37 305.47,204.63 303.91,204.63
D10802: length 244.5
  L34_DIG w0.102: v1(303.23,205.43) 303.91,205.43
  L34_DIG w0.104: 303.91,205.43 305.64,205.43 306.13,204.94 312.41,204.94 318.46,198.89 330,198.89 335.21,193.68 340.14,193.68 352.55,181.28 352.55,34.39 357.96,28.98 369.41,28.98 380.08,39.65 381.99,39.65 D108.02
D10803: length 244.5
  L34_DIG w0.102: 303.91,206.23 v1(303.23,206.23)
  L34_DIG w0.104: 303.91,206.23 312.34,206.23 316.66,201.91 328.42,201.91 335.26,195.08 342.81,195.08 353.9,183.99 353.9,168.78 354.9,167.78 354.9,166.07 353.76,164.93 353.76,42.21 359.83,36.14 372.36,36.14 377.86,41.64 383.97,41.64 384.99,40.62 384.99,36.65 D108.03
D10804: length 242.3
  L34_DIG w0.102: 303.91,207.43 299.63,207.43 v1(299.23,207.03)
  L34_DIG w0.104: 303.91,207.43 305.31,207.43 305.78,207.9 311.86,207.9 317.07,202.69 328.97,202.69 335.51,196.15 370.88,196.15 373.09,193.93 373.09,125.22 387.48,110.83 387.48,39.24 D108.04
D10805: length 253.9
  L34_DIG w0.102: v1(299.23,207.83) 299.63,208.23 303.91,208.23
  L34_DIG w0.104: D108.05 390.04,36.68 390.04,113.15 379.4,123.78 379.4,159.57 382.1,162.27 382.1,194.99 380.56,196.52 373.88,196.52 372.96,197.44 335.5,197.44 329.23,203.72 317.61,203.72 313.09,208.23 303.91,208.23
D10806: length 248.7
  L34_DIG w0.102: 303.91,209.43 v1(303.23,209.43)
  L34_DIG w0.104: 303.91,209.43 304.71,209.43 305.47,210.19 311.86,210.19 316.51,205.54 329.57,205.54 334.19,200.92 369.38,200.92 371.5,198.81 380.95,198.81 383.66,196.1 383.66,123.97 392.53,115.11 392.53,39.27 D108.06
D10807: length 258.5
  L34_DIG w0.102: 303.91,210.63 299.63,210.63 v1(299.23,210.23)
  L34_DIG w0.104: D108.07 395.18,36.62 395.18,116.94 385.19,126.92 385.19,197.11 381.58,200.72 372.68,200.72 371.27,202.14 336.06,202.14 332.05,206.14 317.27,206.14 311.99,211.43 305.75,211.43 304.96,210.63 303.91,210.63
D10808: length 258.6
  L34_DIG w0.102: v1(299.23,211.03) 299.63,211.43 303.91,211.43
  L34_DIG w0.104: 303.91,211.43 304.56,211.43 305.15,212.02 312.52,212.02 317.46,207.08 332.83,207.08 336.5,203.41 372.36,203.41 373.96,201.81 382.82,201.81 386.64,197.99 386.64,127.91 397.55,117 397.55,39.33 D108.08
D10809: length 261.3
  L34_DIG w0.102: 303.91,212.63 v1(303.23,212.63)
  L34_DIG w0.104: D108.09 400.06,36.82 400.06,117.52 389.02,128.56 389.02,199.12 385.13,203.01 375.45,203.01 372.28,206.18 335.31,206.18 333.76,207.73 317.62,207.73 317.21,208.14 317.21,209.42 313.34,213.29 306.1,213.29 305.44,212.63 303.91,212.63
D10810: length 260.3
  L34_DIG w0.102: 303.91,213.43 v1(303.23,213.43)
  L34_DIG w0.104: D108.10 402.47,39.49 402.47,117.85 391.12,129.2 391.12,198.97 383.96,206.13 375.17,206.13 373.71,207.6 335.39,207.6 333.41,209.57 318.01,209.57 313.78,213.8 305.65,213.8 305.28,213.43 303.91,213.43
D10811: length 267
  L34_DIG w0.102: 303.91,214.23 v1(303.23,214.23)
  L34_DIG w0.104: D108.11 405.13,36.83 405.13,119.56 393.66,131.03 393.66,200.63 385.68,208.61 335.99,208.61 334.18,210.41 318.43,210.41 313.9,214.95 305.84,214.95 305.12,214.23 303.91,214.23
D10812: length 267.7
  L34_DIG w0.102: 303.91,215.83 v1(303.23,215.83)
  L34_DIG w0.104: D108.12 407.54,39.5 407.54,120.36 395.64,132.26 395.64,202.34 387.33,210.66 374.61,210.66 373.79,211.47 319.66,211.47 315.71,215.43 306.1,215.43 305.69,215.83 303.91,215.83
D10813: length 277.1
  L34_DIG w0.102: v1(299.23,216.63) 299.63,217.03 303.91,217.03
  L34_DIG w0.104: D108.13 410.13,36.91 410.13,120.82 400.04,130.91 400.04,199.9 387.53,212.41 319.8,212.41 315.18,217.03 303.91,217.03
D10814: length 280.8
  L34_DIG w0.102: v1(299.23,217.43) 299.63,217.83 303.91,217.83
  L34_DIG w0.104: D108.14 412.7,39.42 412.7,127.94 405.51,135.13 405.51,197.78 385.81,217.48 354.62,217.48 352.81,215.68 345.31,215.68 344.16,216.84 340.3,216.84 339.45,215.98 320.4,215.98 317.76,218.62 305.54,218.62 304.75,217.83 303.91,217.83
D10815: length 282.6
  L34_DIG w0.102: 303.91,219.03 v1(303.23,219.03)
  L34_DIG w0.104: 303.91,219.03 335.9,219.03 337.03,217.9 347.59,217.9 350.25,220.56 353.22,220.56 353.63,220.15 375.61,220.15 376.94,221.48 384.15,221.48 410.74,194.89 410.74,133.3 415.41,128.63 415.41,36.71 D108.15
D10816: length 282.4
  L34_DIG w0.102: 303.91,219.83 v1(303.23,219.83)
  L34_DIG w0.104: D108.16 417.9,39.3 417.9,130.44 415.84,132.5 415.84,192.62 386.12,222.35 337.02,222.35 334.7,220.03 329.5,220.03 328.82,220.71 305.76,220.71 304.88,219.83 303.91,219.83
D10901: length 157.1
  L09_DIG w0.079: v3(327.57,279.06) 327.57,277.65 327.73,277.5 327.95,277.5 328.39,277.93 328.39,302.35 332.25,306.21 408.25,306.21 424.78,322.74 424.78,334.46 422.43,336.82 420.23,336.82 418.26,334.85 418.26,334.32 418.57,334.01 420.37,334.01 D109.01
  BOTTOM w0.117: R126.2 v3(327.57,279.06)
D10902: length 153
  L07_DIG w0.079: D109.02 418.16,329.26 417.04,329.26 416.77,328.98 416.77,303.17 407.65,294.06 376.56,294.06 367.54,303.07 367.54,313.7 366.55,314.69 362.09,314.69 360.71,313.31 360.71,304.69 353.5,297.48 346.99,297.48 344.24,294.73 344.24,277.8 344.55,277.5 344.77,277.5 344.93,277.65 v3(344.93,279.06)
  BOTTOM w0.117: R124.2 v3(344.93,279.06)
D10903: length 157.1
  L09_DIG w0.079: v3(327.57,275.54) 327.57,276.96 327.73,277.11 328.11,277.11 328.77,277.78 328.77,302.19 332.41,305.83 408.41,305.83 425.17,322.58 425.17,334.62 422.59,337.2 420.07,337.2 417.87,335.01 417.87,334.05 D109.03
  BOTTOM w0.117: R125.2 v3(327.57,275.54)
D10904: length 153
  L07_DIG w0.079: v3(344.93,275.54) 344.93,276.96 344.77,277.11 344.39,277.11 343.86,277.64 343.86,294.89 346.84,297.86 353.34,297.86 360.33,304.85 360.33,313.47 361.93,315.07 366.71,315.07 367.92,313.86 367.92,303.23 376.72,294.44 407.5,294.44 416.38,303.33 416.38,327.84 D109.04
  BOTTOM w0.117: R123.2 v3(344.93,275.54)
D10905: length 157.1
  L09_DIG w0.079: D109.05 410.15,334.07 408.41,334.07 408.07,334.42 408.07,334.95 411.95,338.83 422.82,338.83 428,333.65 428,321.45 409.61,303.06 350.1,303.06 343.55,296.52 343.55,277.86 343.19,277.5 342.97,277.5 342.81,277.65 v3(342.81,279.06)
  BOTTOM w0.117: R118.2 v3(342.81,279.06)
D10906: length 153
  L07_DIG w0.079: v3(329.69,279.06) 329.69,277.65 329.53,277.5 329.31,277.5 329.06,277.75 329.06,294.53 334.35,299.82 351.13,299.82 358.24,306.93 358.24,315.87 359.75,317.38 369.07,317.38 369.94,316.52 369.94,306.29 376.41,299.82 399.39,299.82 406.59,307.02 406.59,328.93 406.8,329.13 407.87,329.13 D109.06
  BOTTOM w0.117: R128.2 v3(329.69,279.06)
D10907: length 157.1
  L09_DIG w0.079: v3(342.81,275.54) 342.81,276.96 342.97,277.11 343.35,277.11 343.94,277.7 343.94,296.36 350.26,302.68 409.77,302.68 428.39,321.29 428.39,333.81 422.98,339.22 411.79,339.22 407.68,335.11 407.68,334.02 D109.07
  BOTTOM w0.117: R117.2 v3(342.81,275.54)
D10908: length 153
  L07_DIG w0.079: D109.08 403.86,330.14 406.21,327.79 406.21,307.18 399.23,300.21 376.57,300.21 370.32,306.45 370.32,316.68 369.23,317.77 359.59,317.77 357.85,316.03 357.85,307.09 350.97,300.21 334.19,300.21 328.68,294.69 328.68,277.59 329.15,277.11 329.53,277.11 329.69,276.96 v3(329.69,275.54)
  BOTTOM w0.117: R127.2 v3(329.69,275.54)
D10909: length 153
  L09_DIG w0.079: v3(299.21,275.54) 299.21,276.96 299.05,277.11 298.67,277.11 298.1,277.69 298.1,307.34 310.17,319.4 352.45,319.4 372.18,339.13 396.2,339.13 400.01,335.32 400.01,334.05 D109.09
  BOTTOM w0.117: R136.2 v3(299.21,275.54)
D10910: length 157.1
  L07_DIG w0.079: D109.10 396.43,327.85 396.43,310.03 389.74,303.35 377.27,303.35 372.03,308.59 372.03,318.82 370.33,320.52 357.77,320.52 356.16,318.91 356.16,309.13 350.38,303.35 321.94,303.35 313.55,294.97 313.55,277.8 312.87,277.11 312.49,277.11 312.33,276.96 v3(312.33,275.54)
  BOTTOM w0.117: R130.2 v3(312.33,275.54)
D10911: length 153
  L09_DIG w0.079: v3(299.21,279.06) 299.21,277.65 299.05,277.5 298.83,277.5 298.48,277.84 298.48,307.18 310.33,319.02 352.61,319.02 372.33,338.75 396.04,338.75 399.63,335.16 399.63,334.36 399.15,333.88 397.38,333.88 D109.11
  BOTTOM w0.117: R135.2 v3(299.21,279.06)
D10912: length 157.1
  L07_DIG w0.079: D109.12 394.82,329.08 395.9,329.08 396.04,328.94 396.04,310.19 389.58,303.73 377.43,303.73 372.42,308.75 372.42,318.98 370.49,320.9 357.61,320.9 355.78,319.07 355.78,309.29 350.22,303.73 321.78,303.73 313.17,295.13 313.17,277.96 312.71,277.5 312.49,277.5 312.33,277.65 v3(312.33,279.06)
  BOTTOM w0.117: R129.2 v3(312.33,279.06)
D10913: length 153
  L09_DIG w0.079: D109.13 389.9,334 389.9,335.57 388.58,336.89 374.75,336.89 373.05,335.19 373.05,325.25 376.29,322.02 380.84,322.02 383.44,319.42 383.44,314.03 380.97,311.56 322.19,311.56 313.29,302.67 313.29,277.74 313.91,277.11 314.29,277.11 314.45,276.96 v3(314.45,275.54)
  BOTTOM w0.117: R132.2 v3(314.45,275.54)
D10914: length 157.1
  L07_DIG w0.079: v3(297.09,275.54) 297.09,276.96 297.25,277.11 297.63,277.11 298.27,277.75 298.27,295.9 307.96,305.59 346.61,305.59 353.82,312.8 353.82,320.8 355.55,322.54 372.01,322.54 374.25,320.3 374.25,311.39 376.57,309.07 383.98,309.07 386.28,311.37 386.28,327.86 D109.14
  BOTTOM w0.117: R134.2 v3(297.09,275.54)
D10915: length 153
  L09_DIG w0.079: v3(314.45,279.06) 314.45,277.65 314.29,277.5 314.07,277.5 313.67,277.89 313.67,302.51 322.34,311.18 381.13,311.18 383.82,313.87 383.82,319.58 381,322.4 376.45,322.4 373.44,325.41 373.44,335.03 374.91,336.5 388.42,336.5 389.51,335.41 389.51,334.45 388.91,333.85 387.19,333.85 D109.15
  BOTTOM w0.117: R131.2 v3(314.45,279.06)
D10916: length 157.1
  L07_DIG w0.079: D109.16 384.6,329.14 385.65,329.14 385.9,328.89 385.9,311.53 383.82,309.45 376.73,309.45 374.63,311.55 374.63,320.46 372.17,322.92 355.39,322.92 353.44,320.96 353.44,312.96 346.45,305.98 307.8,305.98 297.88,296.06 297.88,277.91 297.47,277.5 297.25,277.5 297.09,277.65 v3(297.09,279.06)
  BOTTOM w0.117: R133.2 v3(297.09,279.06)
D11001: length 328.2
  L07_DIG w0.081: D110.01 415.53,359.17 377.79,359.17 377.28,359.68 377.28,364.12 377.81,364.65 422.46,364.65 426.94,360.17 426.94,327.34 422.32,322.72 422.32,293.28 416.13,287.09 400.65,287.09 357.84,244.28 354.67,244.28 353.19,242.8 350.82,242.8 348.11,240.09 338.56,240.09 335.65,237.17 321.61,237.17 317.09,232.66 317.09,225.12 316.02,224.05 305.87,224.05 304.45,222.63 303.91,222.63
  L07_DIG w0.102: 303.91,222.63 300.43,222.63 v1(300.03,223.03)
D11002: length 260.6
  L03_DIG w0.096: D110.02 417.54,348.96 417.54,347.57 418.08,347.03 423.93,347.03 426.89,344.07 426.89,323.51 416.04,312.67 416.04,224.78 408.07,216.81 379.12,216.81 375.3,212.99 340.36,212.99 334.22,219.13 318.97,219.13 316.74,216.89 305.27,216.89 304.62,216.25 303.95,216.25 303.93,216.23 303.91,216.23
  L03_DIG w0.102: 303.91,216.23 302.83,216.23 v1(302.43,216.63)
D11003: length 266.2
  L07_DIG w0.081: 299.63,227.71 299.63,228.17 302.94,231.48 302.94,233.98 311.11,242.14 323.58,242.14 325.7,240.03 330.37,240.03 331.39,241.05 339.24,241.05 344.32,246.13 354.12,246.13 354.98,246.99 354.98,248.33 354.02,249.29 348.58,249.29 348.2,249.67 348.2,250.19 348.59,250.59 361.28,250.59 399.2,288.51 414.71,288.51 420.75,294.55 420.75,322.77 425.73,327.75 425.73,359.6 424.4,360.93 423.69,360.93 422.92,360.15 422.92,347.48 422.26,346.83 418.41,346.83 417.85,347.39 417.85,351.77 D110.03
  L07_DIG w0.102: v1(299.23,223.83) 299.63,224.23 299.63,227.71
D11004: length 260.6
  L03_DIG w0.096: D110.04 415.11,349.43 416.64,349.43 417.17,348.9 417.17,347.42 417.93,346.66 423.77,346.66 426.52,343.92 426.52,323.67 415.68,312.82 415.68,224.93 407.92,217.18 378.96,217.18 375.15,213.36 340.51,213.36 334.38,219.49 318.82,219.49 316.58,217.26 305.11,217.26 304.47,216.61 303.95,216.61 303.93,216.63 303.91,216.63
  L03_DIG w0.102: 303.91,216.63 v1(303.23,216.63)
D11005: length 225
  L07_DIG w0.081: D110.05 412.65,351.89 412.65,346.91 415.56,344 423.05,344 424.3,342.75 424.3,328.08 419.22,323 419.22,295.36 413.65,289.79 397.93,289.79 361.53,253.38 334.07,253.38 332.25,251.56 329.59,251.56 328.77,252.37 319.48,252.37 301.83,234.73 301.83,232.09 298.83,229.09 298.83,227.71
  L07_DIG w0.102: v1(298.43,223.83) 298.83,224.23 298.83,227.71
